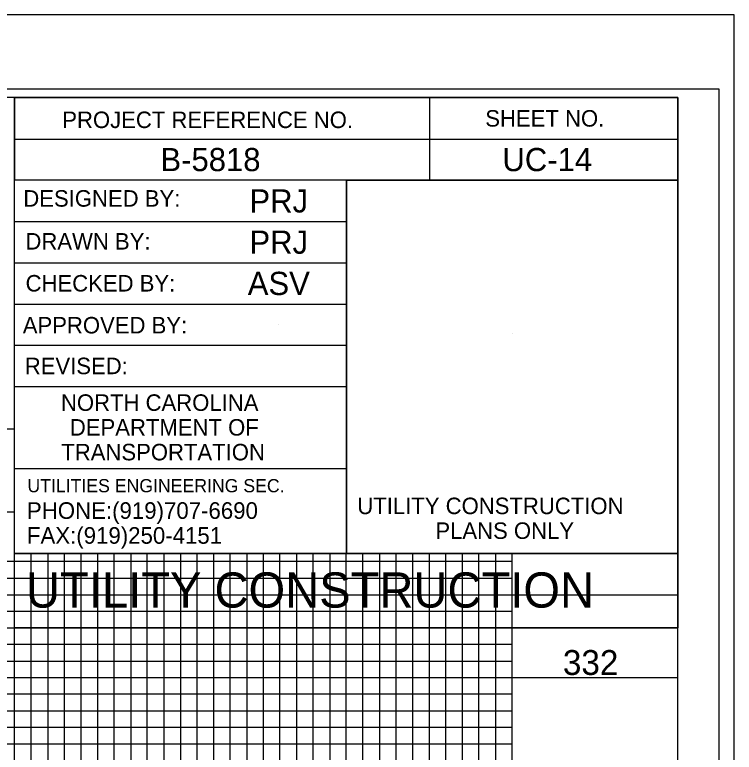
# Model space of a CAD drawing. Extents: x 3814791 to 3815465, y 1224203 to 1224643.
# Drawn here: x 3815378.1 to 3815464.9, y 1224554.2 to 1224643.2 of the extents above; entities that cross this region are included whole.
import ezdxf

# ---------------------------------------------------------------- set-up
doc = ezdxf.new("R2010")
doc.units = 0
for name, color, linetype in [('Exist Roads EOP', 7, 'Continuous'), ('General Text and Text Box and Leader Line', 7, 'Continuous'), ('Pattern 49', 7, 'Continuous'), ('Profile Utility Text', 7, 'Continuous'), ('Prop 8 In Water Line (St)', 7, 'Continuous'), ('Scratch_Level_1', 7, 'Continuous'), ('Scratch_Level_9', 7, 'Continuous'), ('Sheet Data Field CELL', 7, 'Continuous')]:
    doc.layers.add(name, color=color, linetype=linetype)

msp = doc.modelspace()

# ---------------------------------------------------------------- linework, layer by layer
at = {"layer": 'Exist Roads EOP'}
for p, q in [((3815378.107, 1224623.187), (3815378.132, 1224633.207)), ((3815378.132, 1224633.207), (3815458.107, 1224633.207)), ((3815378.132, 1224623.252), (3815378.132, 1224633.207)), ((3815428.137, 1224633.187), (3815428.137, 1224623.232)), ((3815458.107, 1224633.207), (3815458.107, 1224623.252)), ((3815378.132, 1224628.212), (3815458.127, 1224628.212)), ((3815403.122, 1224625.732), (3815403.122, 1224625.732)), ((3815443.122, 1224625.732), (3815443.122, 1224625.732)), ((3815458.107, 1224623.252), (3815378.132, 1224623.252)), ((3815409.937, 1224620.742), (3815409.937, 1224620.742)), ((3815378.132, 1224618.252), (3815418.137, 1224618.252)), ((3815409.937, 1224615.762), (3815409.937, 1224615.762)), ((3815378.132, 1224613.272), (3815418.137, 1224613.272)), ((3815409.937, 1224610.787), (3815409.937, 1224610.787)), ((3815378.132, 1224608.292), (3815418.137, 1224608.292)), ((3815409.937, 1224605.807), (3815409.937, 1224605.807)), ((3815438.127, 1224604.747), (3815438.127, 1224604.747)), ((3815378.132, 1224603.317), (3815418.137, 1224603.317)), ((3815378.132, 1224598.332), (3815418.137, 1224598.332)), ((3815378.132, 1224588.457), (3815418.137, 1224588.457)), ((3815438.107, 1224561.207), (3814878.107, 1224561.207)), ((3814878.107, 1224559.207), (3815438.107, 1224559.207))]:
    msp.add_line(p, q, dxfattribs=at)
for points in [[(3815458.107, 1224633.207), (3814858.107, 1224633.207), (3814858.107, 1224213.207), (3815458.107, 1224213.207)], [(3814878.107, 1224633.207), (3814878.107, 1224223.207), (3815438.107, 1224223.207), (3815438.107, 1224578.187), (3815378.107, 1224578.187), (3815378.107, 1224633.207)], [(3815418.137, 1224623.252), (3815458.107, 1224623.252), (3815458.107, 1224578.187), (3815418.137, 1224578.187)]]:
    msp.add_lwpolyline(points, close=True, dxfattribs=at)
for points in [[(3815378.107, 1224223.207), (3815378.107, 1224633.207), (3815388.627, 1224633.207)], [(3815418.137, 1224623.252), (3815418.137, 1224578.187), (3815378.107, 1224578.187), (3815378.107, 1224633.207), (3815418.137, 1224633.207), (3815418.137, 1224633.147)], [(3815378.087, 1224593.207), (3814858.107, 1224593.207), (3814858.107, 1224573.187), (3815458.107, 1224573.187)], [(3815458.107, 1224563.207), (3814858.107, 1224563.207), (3814858.107, 1224583.207), (3815378.087, 1224583.207)], [(3815380.107, 1224223.207), (3815380.107, 1224578.187)], [(3815382.107, 1224578.187), (3815382.107, 1224223.207), (3815384.107, 1224223.207), (3815384.107, 1224578.187)], [(3815386.107, 1224578.187), (3815386.107, 1224223.207), (3815390.107, 1224223.207), (3815390.107, 1224578.187)], [(3815388.107, 1224578.187), (3815388.107, 1224223.207), (3815408.107, 1224223.207), (3815408.107, 1224578.187)], [(3815392.107, 1224578.187), (3815392.107, 1224223.207), (3815394.107, 1224223.207), (3815394.107, 1224578.187)], [(3815396.107, 1224578.187), (3815396.107, 1224223.207), (3815400.107, 1224223.207), (3815400.107, 1224578.187)], [(3815398.107, 1224578.187), (3815398.107, 1224223.207), (3815418.107, 1224223.207), (3815418.107, 1224578.187)], [(3815402.107, 1224578.187), (3815402.107, 1224223.207), (3815404.107, 1224223.207), (3815404.107, 1224578.187)], [(3815406.107, 1224578.187), (3815406.107, 1224223.207), (3815410.107, 1224223.207), (3815410.107, 1224578.187)], [(3815412.107, 1224578.187), (3815412.107, 1224223.207)], [(3815412.107, 1224223.207), (3815414.107, 1224223.207), (3815414.107, 1224578.187)], [(3815416.107, 1224578.187), (3815416.107, 1224223.207), (3815420.107, 1224223.207), (3815420.107, 1224578.187)], [(3815422.107, 1224578.187), (3815422.107, 1224223.207), (3815424.107, 1224223.207), (3815424.107, 1224578.187)], [(3815426.107, 1224578.187), (3815426.107, 1224223.207), (3815430.107, 1224223.207), (3815430.107, 1224578.187)], [(3815428.107, 1224578.187), (3815428.107, 1224223.207)], [(3815432.107, 1224578.187), (3815432.107, 1224223.207), (3815434.107, 1224223.207), (3815434.107, 1224578.187)], [(3815436.107, 1224578.187), (3815436.107, 1224223.207), (3815440.107, 1224223.207)], [(3815438.107, 1224577.207), (3814878.107, 1224577.207), (3814878.107, 1224577.207), (3814878.107, 1224569.207), (3815438.107, 1224569.207)], [(3815438.107, 1224577.207), (3814878.107, 1224577.207), (3814878.107, 1224577.207), (3814878.107, 1224569.207), (3815458.107, 1224569.207)], [(3814878.107, 1224575.207), (3815438.107, 1224575.207)], [(3815438.107, 1224571.207), (3814878.107, 1224571.207)], [(3815438.107, 1224567.207), (3814878.107, 1224567.207), (3814878.107, 1224565.207), (3815438.107, 1224565.207)], [(3815438.107, 1224557.207), (3814878.107, 1224557.207), (3814878.107, 1224555.207), (3815438.107, 1224555.207)]]:
    msp.add_lwpolyline(points, dxfattribs=at)
at = {"layer": 'Pattern 49'}
msp.add_lwpolyline([(3815463.107, 1224634.227), (3814796.507, 1224634.227), (3814796.507, 1224212.187), (3815463.107, 1224212.187)], close=True, dxfattribs=at)
at = {"layer": 'Profile Utility Text'}
msp.add_lwpolyline([(3815378.107, 1224578.187), (3815458.107, 1224578.187), (3815458.107, 1224569.207), (3815416.023, 1224569.207), (3815402.086, 1224569.207), (3815378.107, 1224569.207)], close=True, dxfattribs=at)
at = {"layer": 'Scratch_Level_1'}
msp.add_lwpolyline([(3815464.907, 1224643.207), (3814791.307, 1224643.207), (3814791.307, 1224203.207), (3815464.907, 1224203.207)], close=True, dxfattribs=at)
at = {"layer": 'Sheet Data Field CELL'}
msp.add_lwpolyline([(3815378.107, 1224578.187), (3815458.107, 1224578.187), (3815458.107, 1224569.207), (3815378.107, 1224569.207)], close=True, dxfattribs=at)

# ---------------------------------------------------------------- texts
at = {"layer": 'Exist Roads EOP'}
for s, height, p in [('PROJECT REFERENCE NO.', 1.99161, (3815383.852, 1224629.532)), ('SHEET NO.', 1.9916, (3815434.877, 1224629.707)), ('DESIGNED BY:', 1.99161, (3815379.152, 1224620.047)), ('DRAWN BY:', 1.9916, (3815379.407, 1224614.872)), ('CHECKED BY:', 1.99161, (3815379.427, 1224609.807)), ('APPROVED BY:', 1.99161, (3815379.087, 1224604.747)), ('REVISED:', 1.9916, (3815379.327, 1224599.832)), ('NORTH CAROLINA', 1.99161, (3815383.692, 1224595.407)), ('DEPARTMENT OF', 1.99161, (3815384.767, 1224592.422)), ('TRANSPORTATION', 1.99161, (3815383.732, 1224589.432)), ('UTILITIES ENGINEERING SEC.', 1.59329, (3815379.647, 1224585.58)), ('UTILITY CONSTRUCTION', 1.99161, (3815419.442, 1224582.942)), ('PLANS ONLY', 1.9916, (3815428.857, 1224579.952)), ('UTILITY CONSTRUCTION', 4.25, (3815379.478, 1224571.662))]:
    msp.add_text(s, height=height, rotation=360, dxfattribs=at).set_placement(p)
at = {"layer": 'General Text and Text Box and Leader Line'}
msp.add_text('332', height=3, dxfattribs=at).set_placement((3815444.238, 1224563.537))
at = {"layer": 'Prop 8 In Water Line (St)'}
for s, p in [('B-5818', (3815395.691, 1224624.332)), ('UC-14', (3815436.941, 1224624.332)), ('PRJ', (3815406.429, 1224619.342)), ('PRJ', (3815406.429, 1224614.362)), ('ASV', (3815406.224, 1224609.387))]:
    msp.add_text(s, height=2.8, dxfattribs=at).set_placement(p)
at = {"layer": 'Scratch_Level_9'}
for s, p in [('PHONE:(919)707-6690', (3815379.586, 1224582.373)), ('FAX:(919)250-4151', (3815379.586, 1224579.368))]:
    msp.add_text(s, height=2.00457, rotation=360, dxfattribs=at).set_placement(p)
at = {"layer": 'Sheet Data Field CELL'}
msp.add_text('UTILITY CONSTRUCTION', height=4.25, rotation=360, dxfattribs=at).set_placement((3815379.478, 1224571.662))

doc.saveas('drawing.dxf')
